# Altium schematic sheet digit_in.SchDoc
size A3
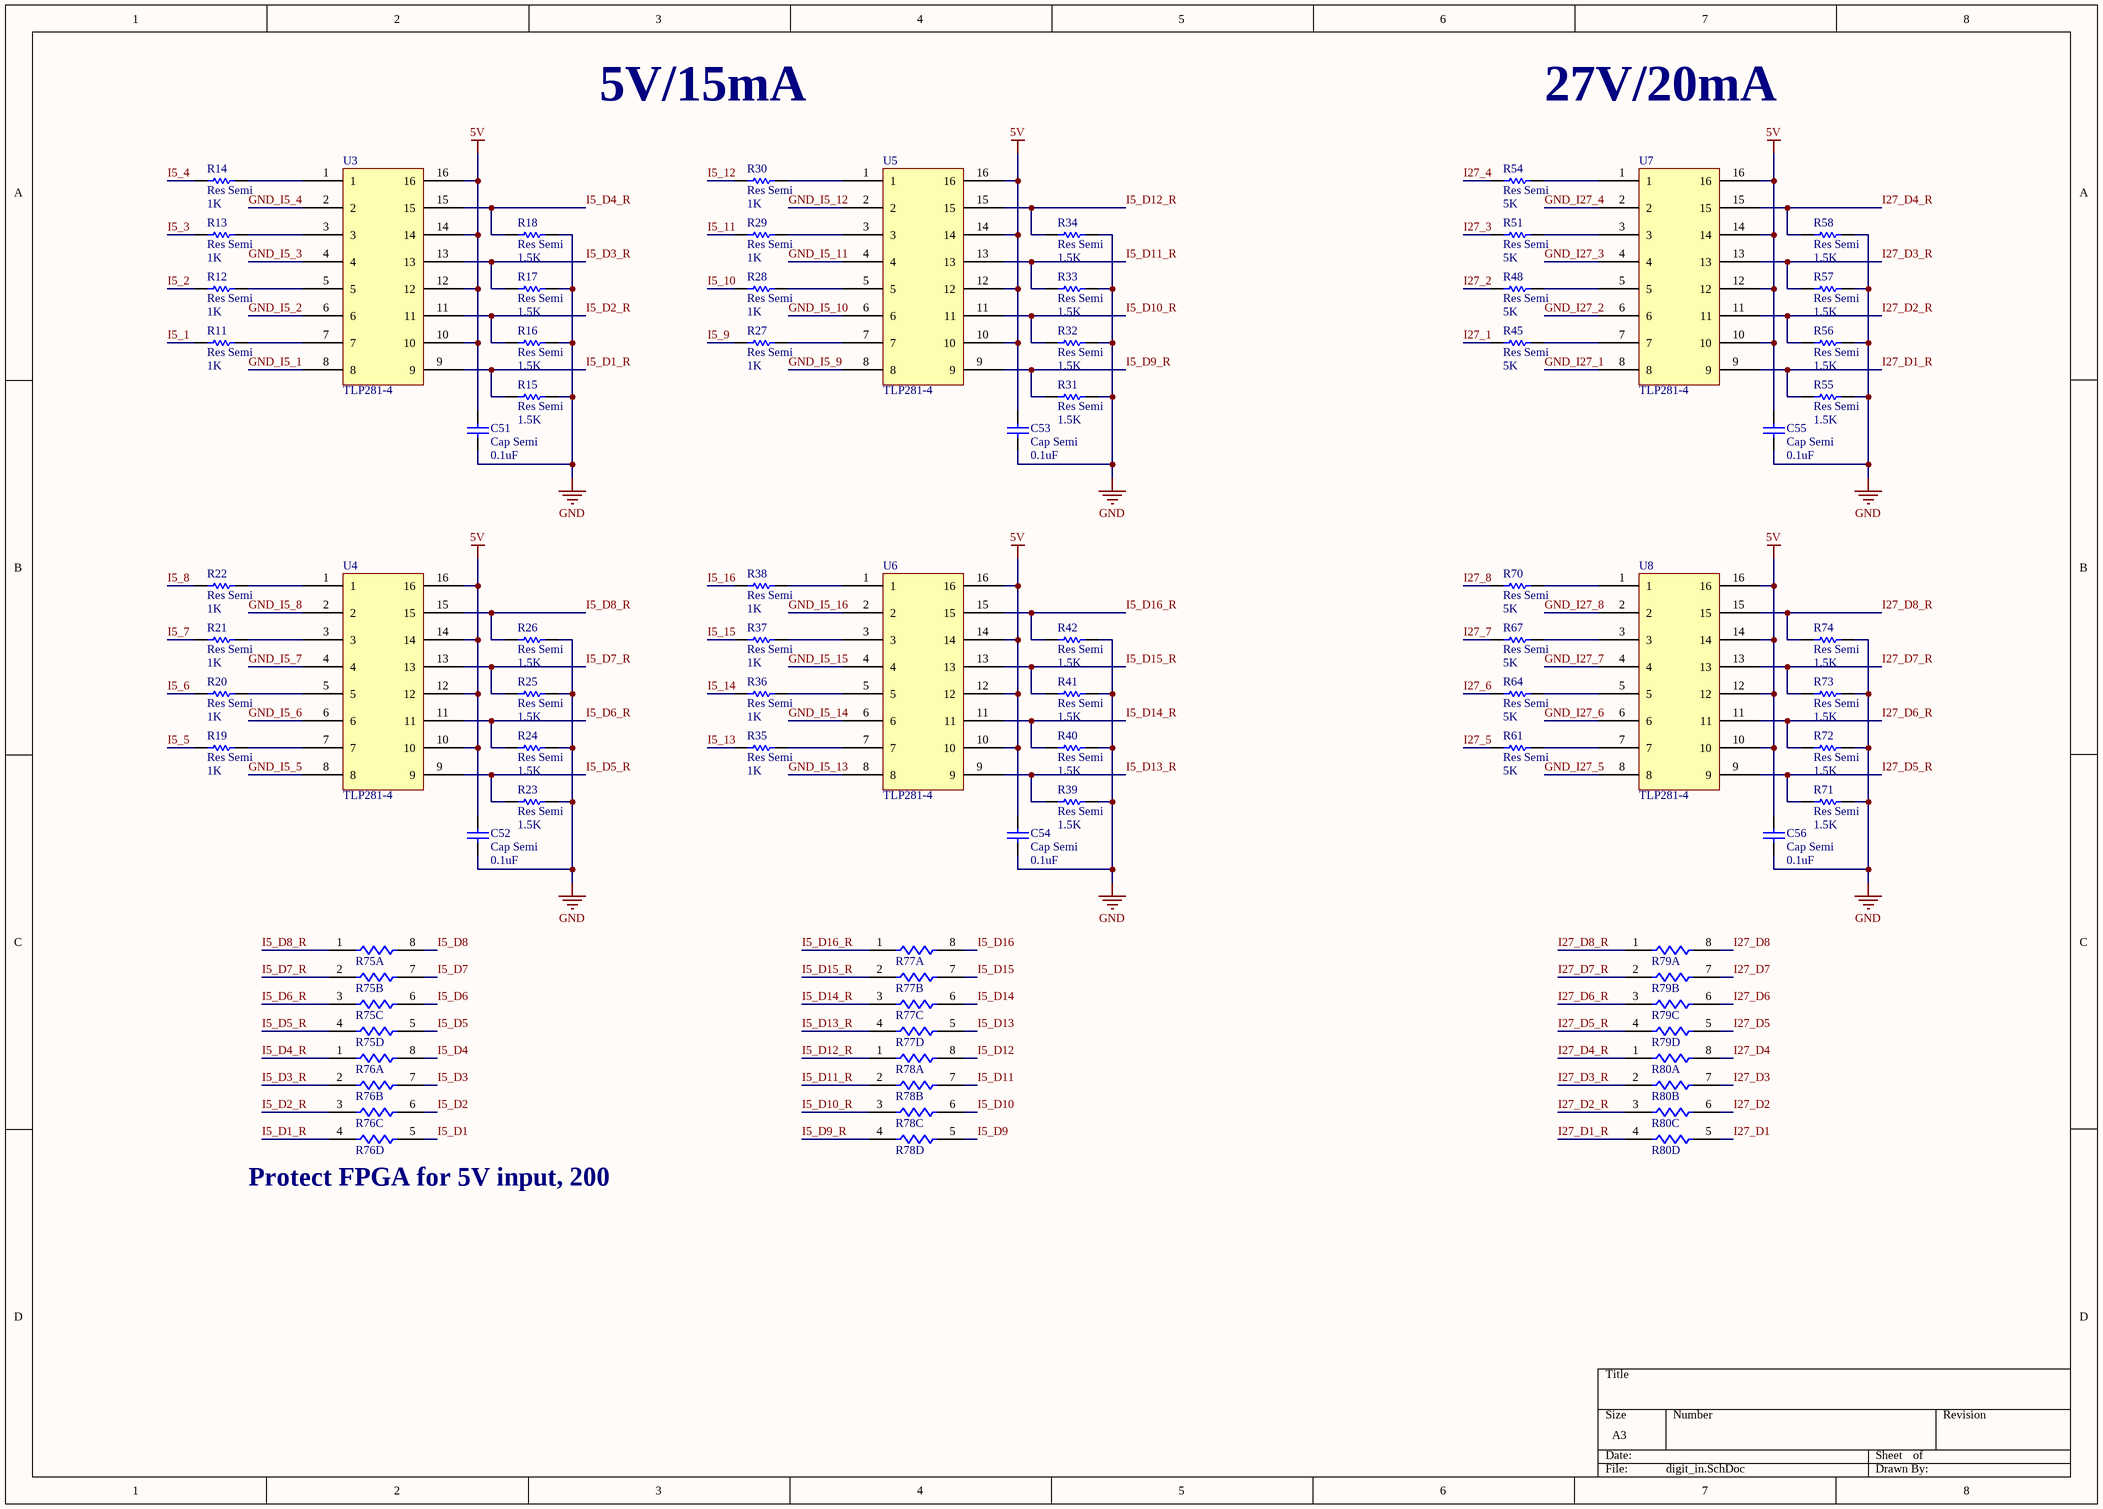
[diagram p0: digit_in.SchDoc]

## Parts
C51  Cap Semi  value 0.1uF  [1608[0603]]
C52  Cap Semi  value 0.1uF  [1608[0603]]
C53  Cap Semi  value 0.1uF  [1608[0603]]
C54  Cap Semi  value 0.1uF  [1608[0603]]
C55  Cap Semi  value 0.1uF  [1608[0603]]
C56  Cap Semi  value 0.1uF  [1608[0603]]
R11  Res Semi  value 1K  [1608[0603]]
R12  Res Semi  value 1K  [1608[0603]]
R13  Res Semi  value 1K  [1608[0603]]
R14  Res Semi  value 1K  [1608[0603]]
R15  Res Semi  value 1.5K  [1608[0603]]
R16  Res Semi  value 1.5K  [1608[0603]]
R17  Res Semi  value 1.5K  [1608[0603]]
R18  Res Semi  value 1.5K  [1608[0603]]
R19  Res Semi  value 1K  [1608[0603]]
R20  Res Semi  value 1K  [1608[0603]]
R21  Res Semi  value 1K  [1608[0603]]
R22  Res Semi  value 1K  [1608[0603]]
R23  Res Semi  value 1.5K  [1608[0603]]
R24  Res Semi  value 1.5K  [1608[0603]]
R25  Res Semi  value 1.5K  [1608[0603]]
R26  Res Semi  value 1.5K  [1608[0603]]
R27  Res Semi  value 1K  [1608[0603]]
R28  Res Semi  value 1K  [1608[0603]]
R29  Res Semi  value 1K  [1608[0603]]
R30  Res Semi  value 1K  [1608[0603]]
R31  Res Semi  value 1.5K  [1608[0603]]
R32  Res Semi  value 1.5K  [1608[0603]]
R33  Res Semi  value 1.5K  [1608[0603]]
R34  Res Semi  value 1.5K  [1608[0603]]
R35  Res Semi  value 1K  [1608[0603]]
R36  Res Semi  value 1K  [1608[0603]]
R37  Res Semi  value 1K  [1608[0603]]
R38  Res Semi  value 1K  [1608[0603]]
R39  Res Semi  value 1.5K  [1608[0603]]
R40  Res Semi  value 1.5K  [1608[0603]]
R41  Res Semi  value 1.5K  [1608[0603]]
R42  Res Semi  value 1.5K  [1608[0603]]
R45  Res Semi  value 5K  [1608[0603]]
R48  Res Semi  value 5K  [1608[0603]]
R51  Res Semi  value 5K  [1608[0603]]
R54  Res Semi  value 5K  [1608[0603]]
R55  Res Semi  value 1.5K  [1608[0603]]
R56  Res Semi  value 1.5K  [1608[0603]]
R57  Res Semi  value 1.5K  [1608[0603]]
R58  Res Semi  value 1.5K  [1608[0603]]
R61  Res Semi  value 5K  [1608[0603]]
R64  Res Semi  value 5K  [1608[0603]]
R67  Res Semi  value 5K  [1608[0603]]
R70  Res Semi  value 5K  [1608[0603]]
R71  Res Semi  value 1.5K  [1608[0603]]
R72  Res Semi  value 1.5K  [1608[0603]]
R73  Res Semi  value 1.5K  [1608[0603]]
R74  Res Semi  value 1.5K  [1608[0603]]
R75  R0603_4  [R0603_4]  (value not drawn)  (parts A,B,C,D of 4)
R76  R0603_4  [R0603_4]  (value not drawn)  (parts A,B,C,D of 4)
R77  R0603_4  [R0603_4]  (value not drawn)  (parts A,B,C,D of 4)
R78  R0603_4  [R0603_4]  (value not drawn)  (parts A,B,C,D of 4)
R79  R0603_4  [R0603_4]  (value not drawn)  (parts A,B,C,D of 4)
R80  R0603_4  [R0603_4]  (value not drawn)  (parts A,B,C,D of 4)
U3  TLP281-4  [TLP281-4]
U4  TLP281-4  [TLP281-4]
U5  TLP281-4  [TLP281-4]
U6  TLP281-4  [TLP281-4]
U7  TLP281-4  [TLP281-4]
U8  TLP281-4  [TLP281-4]

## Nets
5V: C51.2 C52.2 C53.2 C54.2 C55.2 C56.2 U3.10 U3.12 U3.14 U3.16 U4.10 U4.12 U4.14 U4.16 U5.10 U5.12 U5.14 U5.16 U6.10 U6.12 U6.14 U6.16 U7.10 U7.12 U7.14 U7.16 U8.10 U8.12 U8.14 U8.16
GND: C51.1 C52.1 C53.1 C54.1 C55.1 C56.1 R15.2 R16.2 R17.2 R18.2 R23.2 R24.2 R25.2 R26.2 R31.2 R32.2 R33.2 R34.2 R39.2 R40.2 R41.2 R42.2 R55.2 R56.2 R57.2 R58.2 R71.2 R72.2 R73.2 R74.2
GND_I5_1: U3.8
GND_I5_2: U3.6
GND_I5_3: U3.4
GND_I5_4: U3.2
GND_I5_5: U4.8
GND_I5_6: U4.6
GND_I5_7: U4.4
GND_I5_8: U4.2
GND_I5_9: U5.8
GND_I5_10: U5.6
GND_I5_11: U5.4
GND_I5_12: U5.2
GND_I5_13: U6.8
GND_I5_14: U6.6
GND_I5_15: U6.4
GND_I5_16: U6.2
GND_I27_1: U7.8
GND_I27_2: U7.6
GND_I27_3: U7.4
GND_I27_4: U7.2
GND_I27_5: U8.8
GND_I27_6: U8.6
GND_I27_7: U8.4
GND_I27_8: U8.2
I5_1: R11.1
I5_2: R12.1
I5_3: R13.1
I5_4: R14.1
I5_5: R19.1
I5_6: R20.1
I5_7: R21.1
I5_8: R22.1
I5_9: R27.1
I5_10: R28.1
I5_11: R29.1
I5_12: R30.1
I5_13: R35.1
I5_14: R36.1
I5_15: R37.1
I5_16: R38.1
I5_D1: R76.5
I5_D1_R: R15.1 R76.4 U3.9
I5_D2: R76.6
I5_D2_R: R16.1 R76.3 U3.11
I5_D3: R76.7
I5_D3_R: R17.1 R76.2 U3.13
I5_D4: R76.8
I5_D4_R: R18.1 R76.1 U3.15
I5_D5: R75.5
I5_D5_R: R23.1 R75.4 U4.9
I5_D6: R75.6
I5_D6_R: R24.1 R75.3 U4.11
I5_D7: R75.7
I5_D7_R: R25.1 R75.2 U4.13
I5_D8: R75.8
I5_D8_R: R26.1 R75.1 U4.15
I5_D9: R78.5
I5_D9_R: R31.1 R78.4 U5.9
I5_D10: R78.6
I5_D10_R: R32.1 R78.3 U5.11
I5_D11: R78.7
I5_D11_R: R33.1 R78.2 U5.13
I5_D12: R78.8
I5_D12_R: R34.1 R78.1 U5.15
I5_D13: R77.5
I5_D13_R: R39.1 R77.4 U6.9
I5_D14: R77.6
I5_D14_R: R40.1 R77.3 U6.11
I5_D15: R77.7
I5_D15_R: R41.1 R77.2 U6.13
I5_D16: R77.8
I5_D16_R: R42.1 R77.1 U6.15
I27_1: R45.1
I27_2: R48.1
I27_3: R51.1
I27_4: R54.1
I27_5: R61.1
I27_6: R64.1
I27_7: R67.1
I27_8: R70.1
I27_D1: R80.5
I27_D1_R: R55.1 R80.4 U7.9
I27_D2: R80.6
I27_D2_R: R56.1 R80.3 U7.11
I27_D3: R80.7
I27_D3_R: R57.1 R80.2 U7.13
I27_D4: R80.8
I27_D4_R: R58.1 R80.1 U7.15
I27_D5: R79.5
I27_D5_R: R71.1 R79.4 U8.9
I27_D6: R79.6
I27_D6_R: R72.1 R79.3 U8.11
I27_D7: R79.7
I27_D7_R: R73.1 R79.2 U8.13
I27_D8: R79.8
I27_D8_R: R74.1 R79.1 U8.15
NetR11_2: R11.2 U3.7
NetR12_2: R12.2 U3.5
NetR13_2: R13.2 U3.3
NetR14_2: R14.2 U3.1
NetR19_2: R19.2 U4.7
NetR20_2: R20.2 U4.5
NetR21_2: R21.2 U4.3
NetR22_2: R22.2 U4.1
NetR27_2: R27.2 U5.7
NetR28_2: R28.2 U5.5
NetR29_2: R29.2 U5.3
NetR30_2: R30.2 U5.1
NetR35_2: R35.2 U6.7
NetR36_2: R36.2 U6.5
NetR37_2: R37.2 U6.3
NetR38_2: R38.2 U6.1
NetR45_2: R45.2 U7.7
NetR48_2: R48.2 U7.5
NetR51_2: R51.2 U7.3
NetR54_2: R54.2 U7.1
NetR61_2: R61.2 U8.7
NetR64_2: R64.2 U8.5
NetR67_2: R67.2 U8.3
NetR70_2: R70.2 U8.1

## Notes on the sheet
- 5V/15mA
- 27V/20mA
- (near R76) Protect FPGA for 5V input, 200

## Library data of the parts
C51-C56 = Cap Semi: Capacitor (Semiconductor SIM Model)
R11-R42 R45 R48 R51 R54-R58 R61 R64 R67 R70-R74 = Res Semi: Semiconductor Resistor
R75-R80 = R0603_4: Resistor Array - Parts; Code - JEDEC: MS-012-AC; Code - IPC: SO16; Value: 33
